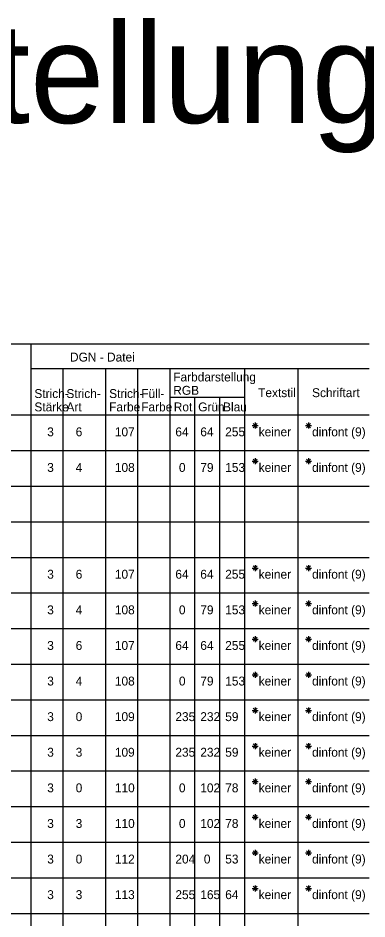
# Model space of a CAD drawing. Extents: x -29 to 48, y -113 to 16.
# Drawn here: x 22.14 to 31.94, y -16.16 to 9.15 of the extents above; entities that cross this region are included whole.
import ezdxf

# ---------------------------------------------------------------- set-up
doc = ezdxf.new("R2010")
doc.units = 0
doc.layers.add('Default', color=7, linetype='Continuous')

msp = doc.modelspace()

# ---------------------------------------------------------------- linework, layer by layer
at = {"layer": 'Default'}
for p, q in [((0, 0), (32, 0)), ((22.5, 0), (22.5, -107)), ((22.5, -0.7), (32, -0.7)), ((23.4, -0.7), (23.4, -89)), ((24.6, -0.7), (24.6, -89)), ((25.5, -0.7), (25.5, -89)), ((26.4, -0.7), (26.4, -89)), ((28.5, -0.7), (28.5, -96)), ((30, -0.7), (30, -96)), ((26.4, -1.5), (28.5, -1.5)), ((27.1, -1.5), (27.1, -89)), ((27.8, -1.5), (27.8, -89)), ((0, -2), (28.338, -2)), ((0, -2), (32, -2)), ((28.741, -2.241), (28.859, -2.359)), ((28.859, -2.241), (28.741, -2.359)), ((28.8, -2.216), (28.8, -2.384)), ((30.241, -2.241), (30.359, -2.359)), ((30.359, -2.241), (30.241, -2.359)), ((30.3, -2.216), (30.3, -2.384)), ((28.716, -2.3), (28.884, -2.3)), ((30.216, -2.3), (30.384, -2.3)), ((0, -3), (32, -3)), ((28.741, -3.241), (28.859, -3.359)), ((28.859, -3.241), (28.741, -3.359)), ((28.8, -3.216), (28.8, -3.384)), ((30.241, -3.241), (30.359, -3.359)), ((30.359, -3.241), (30.241, -3.359)), ((30.3, -3.216), (30.3, -3.384)), ((28.716, -3.3), (28.884, -3.3)), ((30.216, -3.3), (30.384, -3.3)), ((0, -4), (32, -4)), ((0, -5), (32, -5)), ((0, -6), (32, -6)), ((28.716, -6.3), (28.884, -6.3)), ((28.741, -6.241), (28.859, -6.359)), ((28.859, -6.241), (28.741, -6.359)), ((28.8, -6.216), (28.8, -6.384)), ((30.216, -6.3), (30.384, -6.3)), ((30.241, -6.241), (30.359, -6.359)), ((30.359, -6.241), (30.241, -6.359)), ((30.3, -6.216), (30.3, -6.384)), ((0, -7), (32, -7)), ((28.716, -7.3), (28.884, -7.3)), ((28.741, -7.241), (28.859, -7.359)), ((28.859, -7.241), (28.741, -7.359)), ((28.8, -7.216), (28.8, -7.384)), ((30.216, -7.3), (30.384, -7.3)), ((30.241, -7.241), (30.359, -7.359)), ((30.359, -7.241), (30.241, -7.359)), ((30.3, -7.216), (30.3, -7.384)), ((0, -8), (32, -8)), ((28.716, -8.3), (28.884, -8.3)), ((28.741, -8.241), (28.859, -8.359)), ((28.859, -8.241), (28.741, -8.359)), ((28.8, -8.216), (28.8, -8.384)), ((30.216, -8.3), (30.384, -8.3)), ((30.241, -8.241), (30.359, -8.359)), ((30.359, -8.241), (30.241, -8.359)), ((30.3, -8.216), (30.3, -8.384)), ((0, -9), (32, -9)), ((28.716, -9.3), (28.884, -9.3)), ((28.741, -9.241), (28.859, -9.359)), ((28.859, -9.241), (28.741, -9.359)), ((28.8, -9.216), (28.8, -9.384)), ((30.216, -9.3), (30.384, -9.3)), ((30.241, -9.241), (30.359, -9.359)), ((30.359, -9.241), (30.241, -9.359)), ((30.3, -9.216), (30.3, -9.384)), ((0, -10), (32, -10)), ((28.716, -10.3), (28.884, -10.3)), ((28.741, -10.241), (28.859, -10.359)), ((28.859, -10.241), (28.741, -10.359)), ((28.8, -10.216), (28.8, -10.384)), ((30.216, -10.3), (30.384, -10.3)), ((30.241, -10.241), (30.359, -10.359)), ((30.359, -10.241), (30.241, -10.359)), ((30.3, -10.216), (30.3, -10.384)), ((0, -11), (32, -11)), ((28.716, -11.3), (28.884, -11.3)), ((28.741, -11.241), (28.859, -11.359)), ((28.859, -11.241), (28.741, -11.359)), ((28.8, -11.216), (28.8, -11.384)), ((30.216, -11.3), (30.384, -11.3)), ((30.241, -11.241), (30.359, -11.359)), ((30.359, -11.241), (30.241, -11.359)), ((30.3, -11.216), (30.3, -11.384)), ((0, -12), (32, -12)), ((28.716, -12.3), (28.884, -12.3)), ((28.741, -12.241), (28.859, -12.359)), ((28.859, -12.241), (28.741, -12.359)), ((28.8, -12.216), (28.8, -12.384)), ((30.216, -12.3), (30.384, -12.3)), ((30.241, -12.241), (30.359, -12.359)), ((30.359, -12.241), (30.241, -12.359)), ((30.3, -12.216), (30.3, -12.384)), ((0, -13), (32, -13)), ((28.716, -13.3), (28.884, -13.3)), ((28.741, -13.241), (28.859, -13.359)), ((28.859, -13.241), (28.741, -13.359)), ((28.8, -13.216), (28.8, -13.384)), ((30.216, -13.3), (30.384, -13.3)), ((30.241, -13.241), (30.359, -13.359)), ((30.359, -13.241), (30.241, -13.359)), ((30.3, -13.216), (30.3, -13.384)), ((0, -14), (32, -14)), ((28.716, -14.3), (28.884, -14.3)), ((28.741, -14.241), (28.859, -14.359)), ((28.859, -14.241), (28.741, -14.359)), ((28.8, -14.216), (28.8, -14.384)), ((30.216, -14.3), (30.384, -14.3)), ((30.241, -14.241), (30.359, -14.359)), ((30.359, -14.241), (30.241, -14.359)), ((30.3, -14.216), (30.3, -14.384)), ((0, -15), (32, -15)), ((28.716, -15.3), (28.884, -15.3)), ((28.741, -15.241), (28.859, -15.359)), ((28.859, -15.241), (28.741, -15.359)), ((28.8, -15.216), (28.8, -15.384)), ((30.216, -15.3), (30.384, -15.3)), ((30.241, -15.241), (30.359, -15.359)), ((30.359, -15.241), (30.241, -15.359)), ((30.3, -15.216), (30.3, -15.384)), ((0, -16), (32, -16))]:
    msp.add_line(p, q, dxfattribs=at)

# ---------------------------------------------------------------- texts
for s, height, p in [('Leitungsdarstellung: Kälte ', 2.8, (0, 6.2)), ('DGN - Datei', 0.25, (23.6, -0.5)), ('Farbdarstellung', 0.25, (26.5, -1.059)), ('Strich-', 0.25, (22.6, -1.525)), ('Strich-', 0.25, (23.5, -1.525)), ('Strich-', 0.25, (24.7, -1.525)), ('Füll-', 0.25, (25.6, -1.525)), ('RGB', 0.25, (26.5, -1.434)), ('Textstil', 0.25, (28.885, -1.5)), ('Schriftart', 0.25, (30.4, -1.5)), ('Stärke', 0.25, (22.6, -1.9)), ('Art', 0.25, (23.5, -1.9)), ('Farbe', 0.25, (24.7, -1.9)), ('Farbe', 0.25, (25.6, -1.9)), ('Rot', 0.25, (26.515, -1.9)), ('Grün', 0.25, (27.2, -1.9)), ('Blau', 0.25, (27.9, -1.9)), ('3', 0.25, (22.96, -2.6)), ('6', 0.25, (23.76, -2.6)), ('107', 0.25, (24.86, -2.6)), ('64', 0.25, (26.56, -2.6)), ('64', 0.25, (27.26, -2.6)), ('255', 0.25, (27.96, -2.6)), ('keiner', 0.25, (28.9, -2.6)), ('dinfont (9)', 0.25, (30.4, -2.6)), ('3', 0.25, (22.96, -3.6)), ('4', 0.25, (23.76, -3.6)), ('108', 0.25, (24.86, -3.6)), ('0', 0.25, (26.66, -3.6)), ('79', 0.25, (27.26, -3.6)), ('153', 0.25, (27.96, -3.6)), ('keiner', 0.25, (28.9, -3.6)), ('dinfont (9)', 0.25, (30.4, -3.6)), ('3', 0.25, (22.96, -6.6)), ('6', 0.25, (23.76, -6.6)), ('107', 0.25, (24.86, -6.6)), ('64', 0.25, (26.56, -6.6)), ('64', 0.25, (27.26, -6.6)), ('255', 0.25, (27.96, -6.6)), ('keiner', 0.25, (28.9, -6.6)), ('dinfont (9)', 0.25, (30.4, -6.6)), ('keiner', 0.25, (28.9, -7.6)), ('dinfont (9)', 0.25, (30.4, -7.6)), ('3', 0.25, (22.96, -7.6)), ('4', 0.25, (23.76, -7.6)), ('108', 0.25, (24.86, -7.6)), ('0', 0.25, (26.66, -7.6)), ('79', 0.25, (27.26, -7.6)), ('153', 0.25, (27.96, -7.6)), ('3', 0.25, (22.96, -8.6)), ('6', 0.25, (23.76, -8.6)), ('107', 0.25, (24.86, -8.6)), ('64', 0.25, (26.56, -8.6)), ('64', 0.25, (27.26, -8.6)), ('255', 0.25, (27.96, -8.6)), ('keiner', 0.25, (28.9, -8.6)), ('dinfont (9)', 0.25, (30.4, -8.6)), ('3', 0.25, (22.96, -9.6)), ('4', 0.25, (23.76, -9.6)), ('108', 0.25, (24.86, -9.6)), ('0', 0.25, (26.66, -9.6)), ('79', 0.25, (27.26, -9.6)), ('153', 0.25, (27.96, -9.6)), ('keiner', 0.25, (28.9, -9.6)), ('dinfont (9)', 0.25, (30.4, -9.6)), ('3', 0.25, (22.96, -10.6)), ('0', 0.25, (23.76, -10.6)), ('109', 0.25, (24.86, -10.6)), ('235', 0.25, (26.56, -10.6)), ('232', 0.25, (27.26, -10.6)), ('59', 0.25, (27.96, -10.6)), ('keiner', 0.25, (28.9, -10.6)), ('dinfont (9)', 0.25, (30.4, -10.6)), ('3', 0.25, (22.96, -11.6)), ('3', 0.25, (23.76, -11.6)), ('109', 0.25, (24.86, -11.6)), ('235', 0.25, (26.56, -11.6)), ('232', 0.25, (27.26, -11.6)), ('59', 0.25, (27.96, -11.6)), ('keiner', 0.25, (28.9, -11.6)), ('dinfont (9)', 0.25, (30.4, -11.6)), ('3', 0.25, (22.96, -12.6)), ('0', 0.25, (23.76, -12.6)), ('110', 0.25, (24.86, -12.6)), ('0', 0.25, (26.66, -12.6)), ('102', 0.25, (27.26, -12.6)), ('78', 0.25, (27.96, -12.6)), ('keiner', 0.25, (28.9, -12.6)), ('dinfont (9)', 0.25, (30.4, -12.6)), ('3', 0.25, (22.96, -13.6)), ('3', 0.25, (23.76, -13.6)), ('110', 0.25, (24.86, -13.6)), ('0', 0.25, (26.66, -13.6)), ('102', 0.25, (27.26, -13.6)), ('78', 0.25, (27.96, -13.6)), ('keiner', 0.25, (28.9, -13.6)), ('dinfont (9)', 0.25, (30.4, -13.6)), ('3', 0.25, (22.96, -14.6)), ('0', 0.25, (23.76, -14.6)), ('112', 0.25, (24.86, -14.6)), ('204', 0.25, (26.56, -14.6)), ('0', 0.25, (27.36, -14.6)), ('53', 0.25, (27.96, -14.6)), ('keiner', 0.25, (28.9, -14.6)), ('dinfont (9)', 0.25, (30.4, -14.6)), ('3', 0.25, (22.96, -15.6)), ('3', 0.25, (23.76, -15.6)), ('113', 0.25, (24.86, -15.6)), ('255', 0.25, (26.56, -15.6)), ('165', 0.25, (27.26, -15.6)), ('64', 0.25, (27.96, -15.6)), ('keiner', 0.25, (28.9, -15.6)), ('dinfont (9)', 0.25, (30.4, -15.6))]:
    msp.add_text(s, height=height, dxfattribs=at).set_placement(p)

doc.saveas('drawing.dxf')
